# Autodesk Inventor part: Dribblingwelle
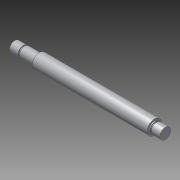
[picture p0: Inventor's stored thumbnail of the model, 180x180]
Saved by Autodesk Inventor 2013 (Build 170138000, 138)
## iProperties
Created: 2012-07
Part Number: Dribblingwelle
Material: Aluminium 6061
Document SubType Name: Modeling
Designer: rYan
Mass: 17.9478 g
Surface Area: 28.0582 cm^2
Volume: 6.62281 cm^3
Density: 2.71 g/cm^3
Author: rYan
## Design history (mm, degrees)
sketch "Skizze1"
  geometry: L1 (-42, 0)-(-42, 3); L2 (-28.26, 3)-(-28.26, 4); L3 (-28.26, 4)-(35.96, 4); L4 (37.2, 3)-(42, 3); L5 (42, 3)-(42, 0); L6 (42, 0)-(-42, 0); L7 (0, 4.8)-(0, -0.8) reference; L8 (-58.8, 0)-(58.8, 0) reference; L9 (-28.26, 3)-(-36.46, 3); L10 (-36.46, 3)-(-36.46, 2.5); L11 (-36.46, 2.5)-(-37.2, 2.5); L12 (-37.2, 2.5)-(-37.2, 3); L13 (-37.2, 3)-(-42, 3); L14 (37.2, 3)-(37.2, 2.5); L15 (37.2, 2.5)-(36.46, 2.5); L16 (36.46, 2.5)-(36.46, 3); L17 (36.46, 3)-(35.96, 3); L18 (35.96, 3)-(35.96, 4); 1 further point
  constraints: 32 end point, 7 parallel, 5 collinear, 5 perpendicular, 1 vertical, 1 other
  dimensions: "d5" = 8 diameter of L3 L6; "d7" = 0.74 distance of L10.end L11.end; "d8" = 5 diameter of L11 L6; "d9" = 6 diameter of L13 L6; "d10" = 8.2 distance between parallel lines of L10 L2; "d11" = 4.8 distance between parallel lines of L1 L12; "d15" = 0.74 distance of L14.end L15.end; "d16" = 5 diameter of L15 L6; "d17" = 4.8 distance of L4.start L4.end; "d18" = 0.5 distance of L16.end L17.end; "d20" = 74.4 distance between parallel lines of L14 L12
revolve "Umdrehung1" sketch "Skizze1" stored, may be unused: angle "d6" = 90 deg
node "Volumenkörper1"
